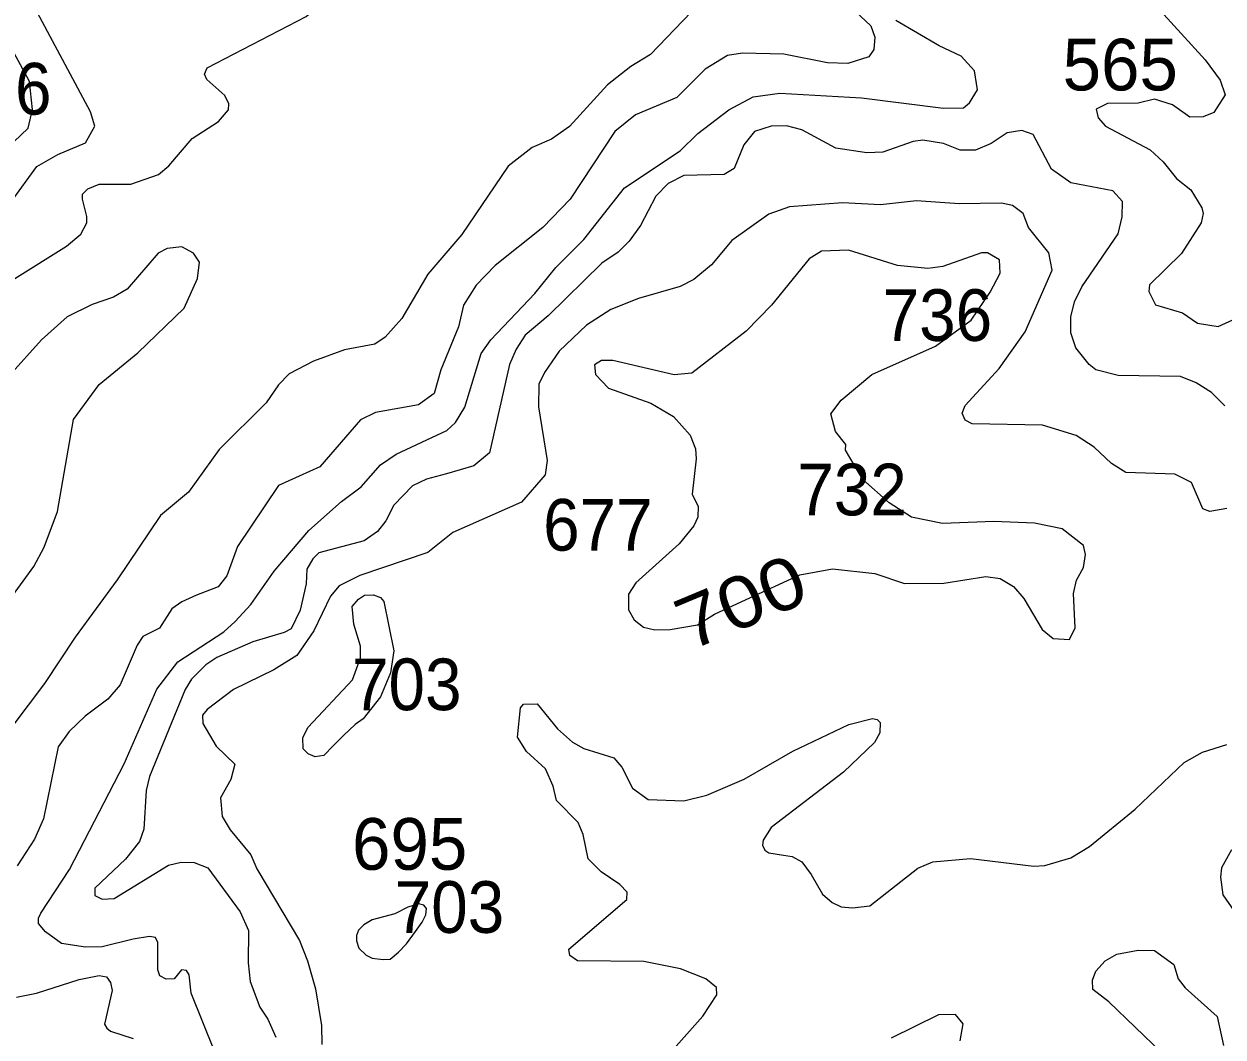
# Model space of a CAD drawing. Extents: x 499.9 to 555.3, y 9281.5 to 9336.8.
# Drawn here: x 546.505 to 550.218, y 9285.393 to 9288.53 of the extents above; entities that cross this region are included whole.
import ezdxf
from ezdxf.enums import TextEntityAlignment as Align

# ---------------------------------------------------------------- set-up
doc = ezdxf.new("R2010")
doc.units = 0
doc.header["$LTSCALE"] = 0.064
doc.layers.add('1', color=7, linetype='Continuous', lineweight=25)
doc.layers.add('2', color=7, linetype='Continuous', lineweight=13)
doc.layers.add('21', color=7, linetype='Continuous')
doc.layers.add('61', color=7, linetype='Continuous')

msp = doc.modelspace()

# ---------------------------------------------------------------- linework, layer by layer
at = {"layer": '1'}
for points in [[(546.4645, 9287.9794), (546.5447, 9288.0889), (546.6099, 9288.1257), (546.695, 9288.1621), (546.7241, 9288.2133), (546.7105, 9288.2575), (546.499, 9288.6545)], [(549.0481, 9288.5982), (549.1274, 9288.5238), (549.1399, 9288.4894), (549.1368, 9288.4504), (549.121, 9288.4285), (549.0566, 9288.4075), (548.9932, 9288.4093), (548.8582, 9288.4361), (548.7299, 9288.4392), (548.6837, 9288.4327), (548.6143, 9288.3903), (548.5268, 9288.302), (548.3988, 9288.248), (548.3347, 9288.1971), (548.1968, 9287.9874), (548.1116, 9287.8992), (547.9643, 9287.7819), (547.9049, 9287.7207), (547.8658, 9287.6594), (547.8509, 9287.5918), (547.7956, 9287.4588), (547.7756, 9287.3853), (547.7262, 9287.3506), (547.5935, 9287.3266), (547.5474, 9287.3037), (547.4213, 9287.1583), (547.2927, 9287.1005), (547.1657, 9286.912), (547.1332, 9286.8207), (547.106, 9286.7871), (547.0388, 9286.7613), (546.9939, 9286.7408), (546.9624, 9286.7191), (546.9247, 9286.6586), (546.8733, 9286.6331), (546.8552, 9286.6062), (546.8026, 9286.4833), (546.764, 9286.4387), (546.6942, 9286.3861), (546.6449, 9286.3384), (546.6104, 9286.2913), (546.5654, 9286.0687), (546.5369, 9286.0051), (546.4835, 9285.9223)], [(546.4813, 9285.516), (546.5437, 9285.5285), (546.6758, 9285.5709), (546.7377, 9285.5829), (546.7602, 9285.5786), (546.7726, 9285.5618), (546.778, 9285.537), (546.7537, 9285.4326), (546.761, 9285.4197), (546.7726, 9285.4107), (546.843, 9285.3884)]]:
    msp.add_lwpolyline(points, dxfattribs=at)
at = {"layer": '2'}
for points in [[(547.0708, 9288.3578), (547.0639, 9288.3746), (547.0716, 9288.3944), (547.3791, 9288.5528), (547.4149, 9288.5843), (547.4388, 9288.6567)], [(548.6032, 9288.5809), (548.5707, 9288.5664), (548.4454, 9288.435), (548.3846, 9288.3984), (548.3117, 9288.3409), (548.1943, 9288.2128)], [(550.0252, 9288.5706), (550.1632, 9288.4191), (550.2096, 9288.3563), (550.2249, 9288.3103), (550.1904, 9288.256), (550.1568, 9288.2419), (550.1155, 9288.2408), (550.0617, 9288.2799), (550.0062, 9288.2973), (549.9553, 9288.285), (549.8606, 9288.2833), (549.8252, 9288.2665), (549.8314, 9288.2389), (549.8546, 9288.2138), (549.9928, 9288.1404), (550.0334, 9288.1032), (550.0747, 9288.051), (550.119, 9288.0158), (550.153, 9287.9604), (550.1572, 9287.9426), (550.1508, 9287.9141), (550.0893, 9287.8193), (549.9908, 9287.7219), (549.9891, 9287.7017), (550.0092, 9287.6601), (550.0927, 9287.635), (550.1392, 9287.6037), (550.2035, 9287.5929), (550.3374, 9287.6535)], [(546.5714, 9285.7181), (546.5497, 9285.7439), (546.5501, 9285.7603), (546.5567, 9285.7767), (546.6452, 9285.9119), (546.8148, 9286.239), (546.9159, 9286.4696), (546.9808, 9286.5547), (547.1237, 9286.6477), (547.1592, 9286.6794), (547.2071, 9286.7322), (547.2795, 9286.8348), (547.387, 9286.961), (547.4878, 9287.0508), (547.5491, 9287.0964), (547.6093, 9287.1643), (547.6578, 9287.1981), (547.8139, 9287.2707), (547.8409, 9287.2959), (547.8704, 9287.3428), (547.921, 9287.5091), (547.9505, 9287.5517), (548.0874, 9287.695), (548.1517, 9287.7753), (548.239, 9287.8626), (548.3644, 9288.0226), (548.5371, 9288.1369), (548.592, 9288.1904), (548.6877, 9288.2638), (548.7633, 9288.3039), (548.8457, 9288.3151), (549.099, 9288.3008), (549.3529, 9288.269), (549.415, 9288.2706), (549.4331, 9288.2851), (549.4583, 9288.3254), (549.4482, 9288.3849), (549.4076, 9288.43), (549.339, 9288.4623), (549.2051, 9288.5407)], [(546.4735, 9288.1644), (546.5174, 9288.2074), (546.5315, 9288.2651), (546.5216, 9288.3519), (546.4732, 9288.4414)], [(546.324, 9287.647), (546.6364, 9287.8413), (546.6813, 9287.8792), (546.6989, 9287.914), (546.699, 9287.9341), (546.686, 9287.9878), (546.6863, 9288.0032), (546.7026, 9288.0196), (546.7379, 9288.0333), (546.836, 9288.0342), (546.921, 9288.0634), (546.9535, 9288.0907), (547.0259, 9288.1755), (547.1069, 9288.2283), (547.1379, 9288.2643), (547.1393, 9288.2829), (547.1269, 9288.3087), (547.0708, 9288.3578)], [(550.2241, 9287.3473), (550.1828, 9287.3887), (550.1352, 9287.418), (550.0866, 9287.4378), (549.8941, 9287.4416), (549.8246, 9287.4585), (549.8035, 9287.4754), (549.7626, 9287.5265), (549.7469, 9287.5734), (549.7472, 9287.6231), (549.7583, 9287.6696), (549.7816, 9287.7162), (549.8937, 9287.8803), (549.9057, 9287.9323), (549.9073, 9287.9801), (549.8774, 9288.0132), (549.7471, 9288.0378), (549.6876, 9288.0803), (549.6303, 9288.1875), (549.5955, 9288.2002), (549.5497, 9288.1928), (549.5001, 9288.1592), (549.4515, 9288.1386), (549.4047, 9288.1387), (549.3528, 9288.1593), (549.2884, 9288.1703), (549.2582, 9288.1654), (549.1645, 9288.1326), (549.1149, 9288.1306), (549.0195, 9288.145), (548.9137, 9288.2023), (548.8666, 9288.2147), (548.8189, 9288.2131), (548.7668, 9288.1973), (548.7343, 9288.1551), (548.7044, 9288.0818), (548.6737, 9288.0636), (548.5484, 9288.0602), (548.5001, 9288.036), (548.4619, 9287.9969), (548.414, 9287.9062), (548.3796, 9287.8568), (548.3446, 9287.8234), (548.2943, 9287.7893), (548.1281, 9287.6259), (548.0572, 9287.5659), (548.0295, 9287.5225), (548.0088, 9287.4748)], [(548.1943, 9288.2128), (548.1387, 9288.1731), (548.0791, 9288.147), (548.0045, 9288.0895), (547.8607, 9287.8775), (547.7558, 9287.7548), (547.6745, 9287.6181), (547.6233, 9287.5604), (547.5917, 9287.5386), (547.4972, 9287.5206), (547.4009, 9287.4853), (547.3261, 9287.4461), (547.2926, 9287.4127), (547.2543, 9287.357), (547.1091, 9287.2119), (547.0139, 9287.0801), (546.9276, 9287.0079), (546.7933, 9286.8085), (546.6635, 9286.6306), (546.568, 9286.4874), (546.419, 9286.2906)], [(550.2298, 9287.0295), (550.1775, 9287.02), (550.1556, 9287.0283), (550.1205, 9287.1096), (550.069, 9287.1357), (549.9172, 9287.1408), (549.8732, 9287.1687), (549.8197, 9287.2197), (549.7636, 9287.2554), (549.6588, 9287.2873), (549.4411, 9287.2918), (549.4201, 9287.3024), (549.4109, 9287.3242), (549.4202, 9287.3479), (549.5248, 9287.4629), (549.6054, 9287.5764), (549.6891, 9287.7671), (549.6785, 9287.821), (549.6164, 9287.8997), (549.5994, 9287.9431), (549.5668, 9287.9679), (549.5319, 9287.9745), (549.4007, 9287.973), (549.2689, 9287.9826), (549.1571, 9287.9698), (549.04, 9287.9762), (548.8755, 9287.9632), (548.812, 9287.9407), (548.6969, 9287.8588), (548.6343, 9287.7836), (548.5796, 9287.7386), (548.5371, 9287.7168), (548.4084, 9287.6801), (548.3226, 9287.6459), (548.2471, 9287.5966), (548.1621, 9287.5167), (548.1164, 9287.4509), (548.0992, 9287.4145), (548.0983, 9287.3444), (548.1249, 9287.1779), (548.1186, 9287.1334), (548.0454, 9287.0492), (547.833, 9286.9551), (547.7554, 9286.8934), (547.5449, 9286.8219), (547.4808, 9286.79), (547.4539, 9286.7575), (547.4027, 9286.6501), (547.3497, 9286.574), (547.2789, 9286.5298), (547.1532, 9286.4692), (547.0724, 9286.4068), (547.0574, 9286.389), (547.0583, 9286.3631), (547.0995, 9286.2938), (547.1581, 9286.2375)], [(546.397, 9286.6606), (546.5356, 9286.8494), (546.5674, 9286.9097), (546.609, 9287.02), (546.6576, 9287.3052), (546.7377, 9287.4132), (546.8571, 9287.5114), (547.0008, 9287.6493), (547.0423, 9287.7415), (547.0486, 9287.7919), (547.0297, 9287.8202), (546.9938, 9287.8393), (546.948, 9287.8344), (546.9207, 9287.8202), (546.824, 9287.7084), (546.7816, 9287.6833), (546.7163, 9287.6614), (546.6381, 9287.6229), (546.5593, 9287.5515), (546.4586, 9287.4398)], [(548.0088, 9287.4748), (547.9462, 9287.2019), (547.8976, 9287.161), (547.8134, 9287.137)], [(547.8134, 9287.137), (547.7509, 9287.12), (547.7082, 9287.0997), (547.6507, 9287.0401), (547.6252, 9286.991), (547.6001, 9286.9582), (547.5584, 9286.929), (547.4181, 9286.892), (547.3989, 9286.8737), (547.3805, 9286.8416), (547.3783, 9286.796), (547.3596, 9286.7148), (547.3321, 9286.6569), (547.3103, 9286.6451), (547.2139, 9286.6166), (547.1017, 9286.5684), (547.0675, 9286.5449), (547.0231, 9286.5004), (547.0038, 9286.4689), (546.8934, 9286.1991), (546.8835, 9286.1562), (546.8756, 9286.0368), (546.8627, 9285.9979), (546.8193, 9285.9431), (546.7245, 9285.8538), (546.7237, 9285.831), (546.7467, 9285.8198), (546.7841, 9285.8212), (546.9521, 9285.9245), (546.9919, 9285.934), (547.0313, 9285.9326), (547.0744, 9285.9164), (547.1741, 9285.7801), (547.2006, 9285.722), (547.1987, 9285.6222), (547.2051, 9285.5641), (547.2356, 9285.485), (547.2595, 9285.448), (547.2843, 9285.392)], [(548.4261, 9285.2536), (548.6077, 9285.4573), (548.6501, 9285.5236), (548.6497, 9285.5457), (548.6167, 9285.5727), (548.5381, 9285.6033), (548.4242, 9285.6269), (548.2195, 9285.6283), (548.1954, 9285.6448), (548.1923, 9285.6647), (548.3722, 9285.8187), (548.3731, 9285.841), (548.3498, 9285.8648), (548.2922, 9285.904), (548.2526, 9285.9443), (548.2364, 9286.0194), (548.2211, 9286.0567), (548.1543, 9286.1246), (548.1439, 9286.1697), (548.1196, 9286.2236), (548.0615, 9286.2764), (548.0332, 9286.321), (548.0428, 9286.4121), (548.052, 9286.4239), (548.0943, 9286.4245), (548.1574, 9286.3474), (548.204, 9286.3053), (548.2387, 9286.2857), (548.3315, 9286.2571), (548.3563, 9286.2285), (548.3894, 9286.1634), (548.4377, 9286.1283), (548.5483, 9286.1236), (548.6195, 9286.1413), (548.7352, 9286.1908)], [(548.7352, 9286.1908), (548.8864, 9286.2783), (549.0593, 9286.3607), (549.1323, 9286.3795), (549.1473, 9286.376), (549.157, 9286.3668)], [(549.157, 9286.3668), (549.1558, 9286.3348), (549.1386, 9286.305), (549.0433, 9286.2126), (548.8194, 9286.041), (548.7939, 9286.0022), (548.7925, 9285.9866), (548.7995, 9285.9708), (548.8113, 9285.9631), (548.8571, 9285.9563), (548.8838, 9285.9513), (548.9143, 9285.9355), (548.9429, 9285.8959), (548.9782, 9285.8355), (549.0077, 9285.8089), (549.0353, 9285.7953), (549.0703, 9285.7925), (549.1249, 9285.7992), (549.2735, 9285.916), (549.3191, 9285.9351), (549.4364, 9285.9452), (549.6327, 9285.9216), (549.6663, 9285.9233), (549.7467, 9285.9479), (549.8046, 9285.9824), (549.9467, 9286.0979), (550.0983, 9286.2423), (550.1552, 9286.2744), (550.2306, 9286.2987)], [(547.1581, 9286.2375), (547.1453, 9286.1905), (547.1131, 9286.133), (547.1189, 9286.0756), (547.1434, 9286.0345), (547.2069, 9285.9573)], [(547.2069, 9285.9573), (547.2258, 9285.9134), (547.3577, 9285.6914), (547.3832, 9285.6285), (547.4073, 9285.5419), (547.4262, 9285.428), (547.4275, 9285.3691)], [(550.245, 9285.9723), (550.2137, 9285.9162), (550.2101, 9285.8879), (550.2183, 9285.8333), (550.2526, 9285.782)], [(546.8938, 9285.7043), (546.8431, 9285.6955), (546.7467, 9285.6716), (546.6954, 9285.6704), (546.6213, 9285.6818), (546.5714, 9285.7181)], [(547.0952, 9285.3484), (547.0227, 9285.5282), (547.0168, 9285.5857), (547.008, 9285.5987), (546.9929, 9285.6006), (546.9702, 9285.5732), (546.9452, 9285.572), (546.9256, 9285.5823), (546.9191, 9285.6004), (546.9191, 9285.6856), (546.9117, 9285.7011), (546.8938, 9285.7043)], [(550.2729, 9285.0841), (550.0685, 9285.0636), (550.0069, 9285.0777), (549.9939, 9285.0962), (550.0162, 9285.1778), (550.0473, 9285.2461), (550.0503, 9285.3036), (550.028, 9285.345), (549.8643, 9285.5015), (549.8154, 9285.5396), (549.814, 9285.5688), (549.8249, 9285.5966), (549.8536, 9285.6284), (549.8894, 9285.6488), (549.9553, 9285.662), (550.0064, 9285.6605), (550.0664, 9285.6169), (550.079, 9285.5727), (550.1011, 9285.5454), (550.2005, 9285.4557), (550.2198, 9285.3668)], [(549.4044, 9285.3804), (549.414, 9285.4337), (549.39, 9285.4626), (549.3371, 9285.4612), (549.1904, 9285.3887)]]:
    msp.add_lwpolyline(points, dxfattribs=at)
for points in [[(549.35, 9286.9829), (549.2539, 9287.0028), (549.184, 9287.0474), (549.1032, 9287.1192), (549.0493, 9287.2103), (549.0503, 9287.2275), (549.0185, 9287.2683), (549.0036, 9287.3222), (549.0354, 9287.3648), (549.1303, 9287.4441), (549.3279, 9287.5324), (549.4383, 9287.6126), (549.4969, 9287.6993), (549.5284, 9287.7582), (549.5266, 9287.7991), (549.489, 9287.8208), (549.4707, 9287.8214), (549.3505, 9287.7789), (549.3041, 9287.7725), (549.2101, 9287.7817), (549.0583, 9287.8294), (548.975, 9287.8263), (548.9362, 9287.802), (548.8196, 9287.6588), (548.7415, 9287.5788), (548.5728, 9287.4483), (548.5189, 9287.4432), (548.3287, 9287.4875), (548.2939, 9287.4873), (548.2715, 9287.4739), (548.2751, 9287.4446), (548.3149, 9287.4023), (548.4465, 9287.3552), (548.5159, 9287.3145), (548.5676, 9287.2566), (548.5847, 9287.2137), (548.5864, 9287.1828), (548.5738, 9287.0735), (548.5926, 9287.0354), (548.5921, 9287.0024), (548.5794, 9286.9757), (548.5343, 9286.9195), (548.4001, 9286.7995), (548.377, 9286.7639), (548.3773, 9286.7157), (548.3946, 9286.6849), (548.4234, 9286.6614), (548.4584, 9286.6536), (548.5062, 9286.6551), (548.5905, 9286.6694), (548.6433, 9286.7018), (548.7414, 9286.7472), (548.9074, 9286.8241), (549.0085, 9286.8425), (549.1402, 9286.8276), (549.232, 9286.797), (549.3535, 9286.7979), (549.4842, 9286.8189), (549.5286, 9286.8126), (549.5695, 9286.7876), (549.6012, 9286.7503), (549.6587, 9286.6545), (549.6928, 9286.6268), (549.7433, 9286.6237), (549.7608, 9286.6593), (549.755, 9286.7657), (549.7648, 9286.8077), (549.7861, 9286.8464), (549.7926, 9286.8873), (549.7862, 9286.9144), (549.7197, 9286.9668), (549.6346, 9286.9844), (549.5089, 9286.9892)], [(547.4941, 9286.3266), (547.463, 9286.2949), (547.4337, 9286.2648), (547.4066, 9286.2605), (547.3851, 9286.2691), (547.3699, 9286.2847), (547.3685, 9286.3207), (547.3852, 9286.3517), (547.5226, 9286.4988), (547.5473, 9286.5664), (547.547, 9286.6033), (547.5262, 9286.6711), (547.5208, 9286.7255), (547.5403, 9286.7488), (547.5596, 9286.7614), (547.5874, 9286.7622), (547.6088, 9286.7539), (547.619, 9286.7412), (547.6503, 9286.5884), (547.6397, 9286.5205), (547.6094, 9286.4458), (547.5554, 9286.3779), (547.5302, 9286.3601)], [(547.6171, 9285.6323), (547.6385, 9285.6335), (547.6647, 9285.6549), (547.6896, 9285.681), (547.7169, 9285.719), (547.7383, 9285.7487), (547.749, 9285.7713), (547.7514, 9285.7903), (547.7431, 9285.801), (547.7264, 9285.8046), (547.6932, 9285.7951), (547.6528, 9285.7737), (547.5827, 9285.7559), (547.5577, 9285.7404), (547.5411, 9285.7238), (547.5351, 9285.7072), (547.5351, 9285.6905), (547.5423, 9285.6679), (547.5648, 9285.6466), (547.5827, 9285.637)]]:
    msp.add_lwpolyline(points, close=True, dxfattribs=at)

# ---------------------------------------------------------------- texts
at = {"layer": '21'}
for s, p in [('565', (549.7216, 9288.324)), ('695', (547.5208, 9285.9106))]:
    msp.add_text(s, height=0.16, dxfattribs=at).set_placement(p)
at = {"layer": '21', "width": 0.95}
for s, p in [('636', (546.2509, 9288.2493)), ('736', (549.1642, 9287.5483)), ('732', (548.8999, 9287.0081)), ('677', (548.1126, 9286.8989)), ('703', (547.5208, 9286.4048)), ('703', (547.653, 9285.7152))]:
    msp.add_text(s, height=0.16, dxfattribs=at).set_placement(p)
at = {"layer": '61', "width": 1.15}
msp.add_text('700', height=0.16, rotation=22.696, dxfattribs=at).set_placement((548.7558, 9286.6666), align=Align.CENTER)

doc.saveas('drawing.dxf')
